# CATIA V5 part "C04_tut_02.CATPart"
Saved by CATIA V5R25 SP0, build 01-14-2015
Part number: Part1
Material "Aluminium": density 2710 kg/m3, Young's modulus 7e+10 Pa, Poisson ratio 0.346, thermal expansion 2.36e-05 1/K
Bounding box of the stored display mesh (mm): x 0 to 30, y -110 to 110, z 0 to 240
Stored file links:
  E:\ashutosh\Academics\Catia\CATIA V5-6R2013_partfiles\Tutorials_ver_2\C04_tut_02.CATPart
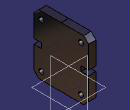
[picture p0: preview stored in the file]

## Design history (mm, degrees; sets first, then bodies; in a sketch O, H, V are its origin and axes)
Body1 (main body), material "Aluminium"
  Sketch1 on yz-plane, origin (0, 0, 0), H (0, 1, 0), V (0, 0, 1)
    line L1 (0, 0) -> (90, 0)
    point P1 (110, 0)
    line L2 (110, 20) -> (110, 110)
    point P2 (110, 220)
    line L3 (90, 0) -> (110, 20)
    point P3 (90, 0)
    point P4 (110, 20)
    point P5 (110, 120)
    line L4 (110, 110) -> (80, 110)
    line L5 (80, 110) -> (80, 130)
    line L6 (80, 130) -> (110, 130)
    point P6 (80, 110)
    point P7 (80, 130)
    point P8 (110, 110)
    point P9 (110, 130)
    axis line L7 (80, 120) -> (-216.0703, 120)
    point P10 (80, 120)
    point P12 (80, 130)
    point P13 (110, 130)
    point P14 (110, 220)
    line L8 (110, 220) -> (110, 130)
    point P15 (90, 240)
    line L9 (90, 240) -> (110, 220)
    point P16 (0, 240)
    line L10 (0, 240) -> (90, 240)
    reference intersected line E1 through (0, 0) direction (0, 1) from zx-plane
    point P19 (0, 0)
    construction line L11 through (0, 0) direction (-1, 0)
    construction line L12 through (0, 0) direction (0, 1)
    point P20 (-110, 0)
    point P21 (-110, 220)
    point P22 (-90, 0)
    point P23 (-110, 20)
    point P24 (-110, 120)
    point P25 (-80, 110)
    point P26 (-80, 130)
    point P27 (-110, 110)
    point P28 (-110, 130)
    point P29 (-80, 120)
    point P30 (-110, 130)
    point P31 (-110, 220)
    point P32 (-90, 240)
    point P33 (0, 240)
    line L13 (0, 0) -> (-90, 0)
    line L14 (-110, 20) -> (-110, 110)
    line L15 (-90, 0) -> (-110, 20)
    line L16 (-110, 110) -> (-80, 110)
    line L17 (-80, 110) -> (-80, 130)
    line L18 (-80, 130) -> (-110, 130)
    line L19 (-110, 220) -> (-110, 130)
    line L20 (-90, 240) -> (-110, 220)
    line L21 (0, 240) -> (-90, 240)
    circle A1 centre (80, 210) radius 10
    point P34 (80, 210)
    circle A2 centre (-80, 210) radius 10
    circle A3 centre (80, 30) radius 10
    circle A4 centre (-80, 30) radius 10
    distance P3 P1 = 20
    angle L3 L1 = 45
    distance L10 L1 = 240
    distance L2 L14 = 220
    length L5 = 20
    distance P34 L10 = 30
    radius A1 = 10
    distance L5 L17 = 160
    horizontal: L1 H, L4 H, L6 H, L7 H
    vertical: L2 V, L5 V
    coincidence: L1 P1, L2 P1, L2 P9, L2 P5, P34 L5, O P19, P9 P13, P16 P33, P28 P30
    equidistance: L4 L6 P5, P4 P2 P5
    midpoint: P10 L5
    symmetry: P6 P12 L7, P8 P13 L7, P4 P14 L7, L2 L8 L7, P3 P15 L7, L3 L9 L7, O P16 L7, L1 L10 L7, O P19 E1, H L11 E1, V L12 E1, P1 P20 E1, P2 P21 E1, P3 P22 E1, P4 P23 E1, P5 P24 E1, P6 P25 E1, P7 P26 E1, P8 P27 E1, P9 P28 E1, P10 P29 E1, P13 P30 E1, P14 P31 E1, P15 P32 E1, P16 P33 E1, L1 L13 E1, L2 L14 E1, L3 L15 E1, L4 L16 E1, L5 L17 E1, L6 L18 E1, L8 L19 E1, L9 L20 E1, L10 L21 E1, A1 A2 L12, A1 A3 L7, A2 A4 L7
  Pad1: profile Sketch1, direction (1, 0, 0), length 30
